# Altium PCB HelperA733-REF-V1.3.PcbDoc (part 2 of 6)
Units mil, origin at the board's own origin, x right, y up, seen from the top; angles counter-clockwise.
Board outline 5905.51 x 4133.86 mil, 2 copper layers (Top, Bottom), stack 12.7 mil thick; 446 components, 341 nets, 1706 pads, 1667 vias.
Unrouted connection lines stored in the file: 1382.
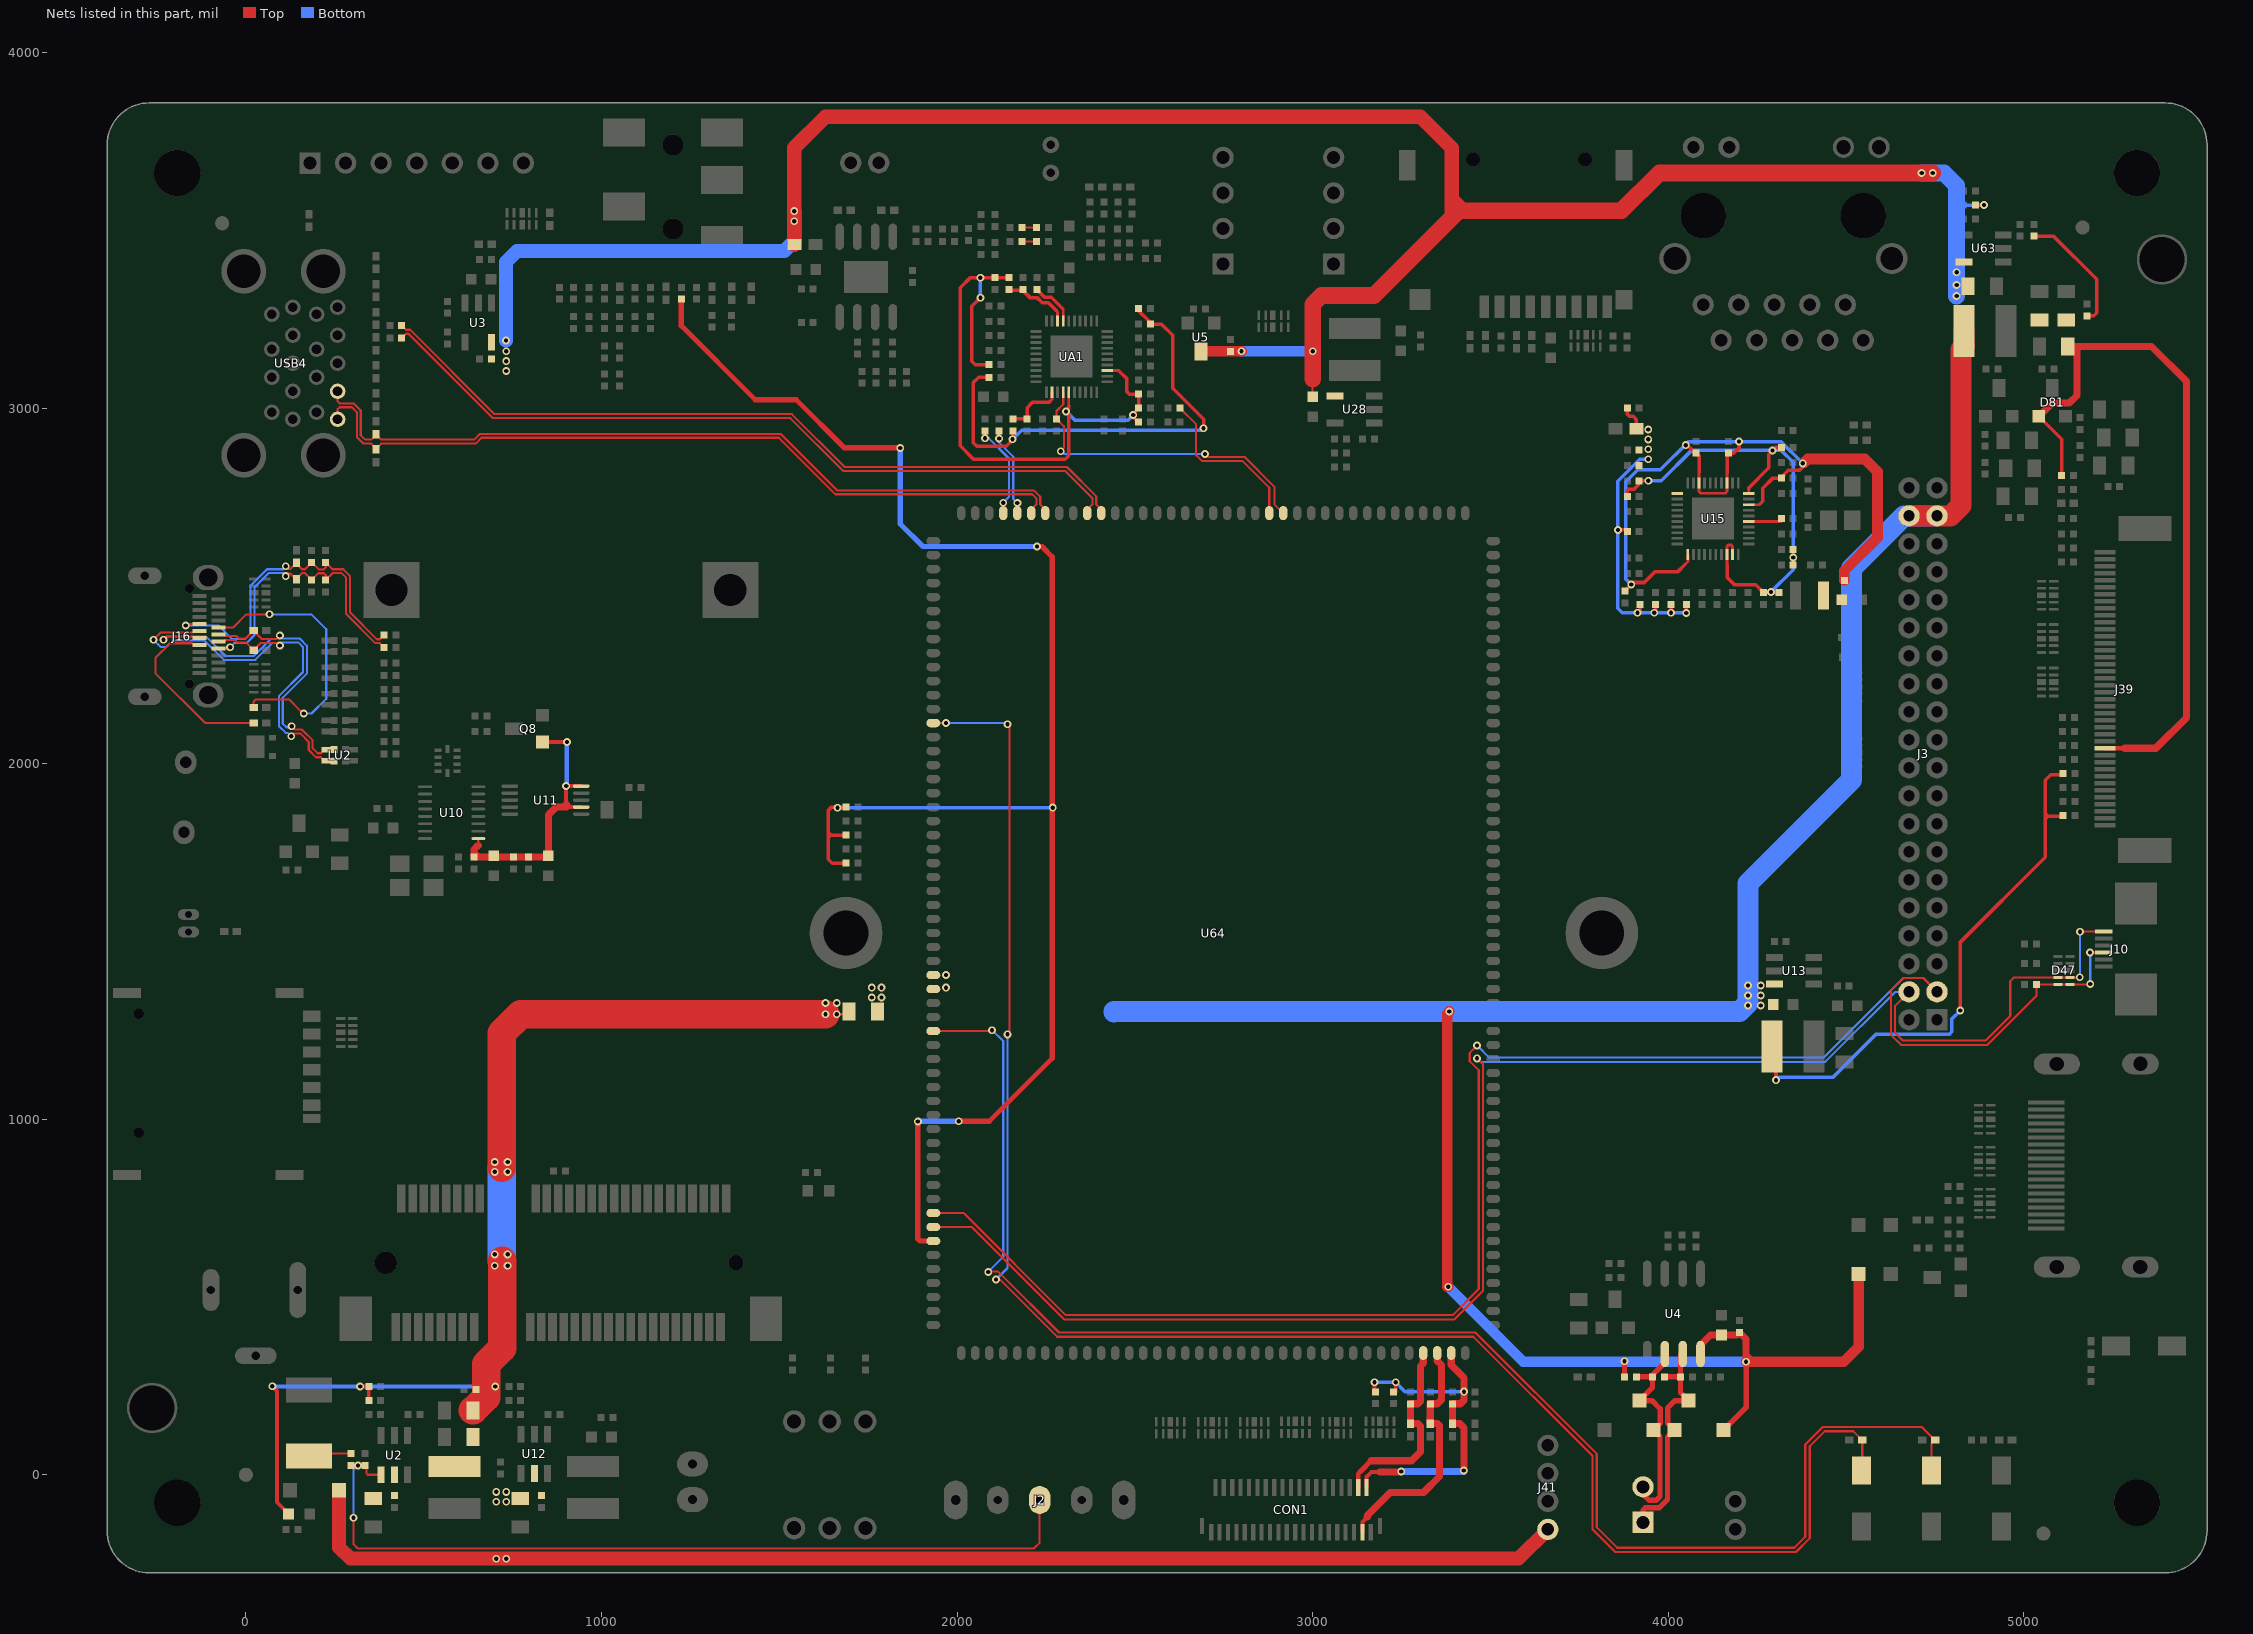
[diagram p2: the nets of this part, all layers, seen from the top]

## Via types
v1: diameter 22, hole 12, Top to Bottom, 1667 vias

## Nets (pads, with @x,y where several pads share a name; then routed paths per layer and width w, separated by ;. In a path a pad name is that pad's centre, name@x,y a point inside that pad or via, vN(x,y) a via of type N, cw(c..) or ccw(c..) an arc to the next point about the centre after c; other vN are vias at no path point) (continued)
5V: C6.1 C35.1 C36.1 C93.1 C95.1 C96.1 C97.1 C216.1 C223.2 C234.1 CU1.2 D3.1 D85.1 D114.2 FB1.2 J3.37 J3.38 L1.2 L4.1 L7.1 R2.1 R42.1 R201.1 R202.1 R210.2 R293.1 U3.5 U4.8 U5.3 U13.6 U28.4 U63.5 | length 18659.5
  Top w6: C96.1@638.43,181.1 638.43,200.34 638.22,200.55 646.65,208.98 C95.1@646.65,240.16 675.46,240.16 684.38,240.16 692.67,248.44 v1(701.28,248.44) ; v1(1629.92,1295.28) v1(1661.42,1295.28) 1698.4,1295.28 1698.4,1300.97 R293.1@1696.22,1303.15 ; C6.1@3000,3031.89 3000,3081.28
  Top w10: v1(74.37,248.93) 87.42,235.88 87.42,-77.05 119.61,-109.24 D3.1@119.61,-110.24 ; v1(321.18,248.36) 345.47,248.36 C93.1@345.47,248.03 R2.1@345.47,208.66 ; L4.1@4291.34,1204.72 4303.13,1204.72 v1(4303.13,1109.95) ; v1(4821.15,1305.5) 4821.15,1497.09 4820.67,1497.09 5060.36,1736.78 5060.36,1844.54 ; R210.2@4864.17,3570.87 v1(4887.9,3570.87) ; R202.1@5110.24,1854.33 5110.24,1852.48 5068.3,1852.48 ; R201.1@5110.24,1972.44 5110.24,1968.99 5075.85,1968.99 5060.36,1953.5 5060.36,1859.62 ; 5060.36,1844.54 5068.3,1852.48 ; 5060.36,1844.54 5060.36,1852.48 ; 5060.36,1852.48 5067.4,1852.48 ; 5060.36,1852.48 5060.36,1859.62 ; 5060.36,1859.62 5067.4,1852.58 5067.4,1852.48 ; 5067.4,1852.48 5068.3,1852.48
  Top w15: R42.1@3876.97,275.59 3876.97,282.12 v1(3877.05,319.56) ; D114.2@4155.61,125.98 4219,189.37 4219,302.88 ; v1(4219,318.12) 4219,302.88 ; 4234.24,318.12 4219,302.88
  Top w20: U4.8@4090.75,339.76 4090.75,365.22 4118.84,393.31 C35.1@4149.61,393.31 ; C35.1@4149.61,394.21 C35.1@4149.61,393.31 ; v1(4219,318.12) 4219,336.95 ; 4234.24,318.12 4234.24,321.71 4219,336.95 ; C35.1@4149.61,393.31 4193.5,393.31 C36.1@4200.79,400.59 4219,382.38 4219,336.95
  Top w23.62: U5.3@2685.96,3158.96 U5.3@2686.61,3159.61
  Top w30: U5.3@2685.96,3158.96 2685.96,3160 v1(2800,3160) ; v1(3381.3,529.12) 3378.88,529.12 3378.27,529.73 3378.27,1297.02 v1(3384.08,1302.83) ; v1(4219,318.12) 4234.24,318.12 4493.57,318.12 4535.43,359.98 D85.1@4535.43,564.86
  Top w40: FB1.2@1542.31,3459.63 1542.31,3732.11 1629.61,3819.41 3302.99,3819.41 3391.21,3731.19 3391.21,3588 ; 3391.21,3588 3391.21,3555.12 3411.68,3555.12 3411.68,3567.54 3391.21,3588
  Top w47.24: 3000,3081.28 v1(3000,3160) 3000,3291.34 3025.02,3316.36 3172.92,3316.36 3411.68,3555.12 3868.72,3555.12 3975.02,3661.42 v1(4712.6,3661.42) v1(4744.09,3661.42)
  Top w59.06: J3.38@4677.17,2696.85 J3.37@4755.91,2696.85 4793.69,2696.85 4823.36,2726.52 4823.36,3165.36 4833,3175 4831.69,3175 L7.1@4831.69,3216.54
  Top w80: C96.1@638.43,181.1 638.87,181.1 675.46,217.69 675.46,240.16 675.46,310.95 720.93,356.42 720.93,601.7 ; 719.79,863.86 719.79,1242.45 772.62,1295.28 v1(1629.92,1295.28)
  Bottom w6: v1(1629.92,1326.77) v1(1629.92,1295.28) v1(1661.42,1326.77)
  Bottom w10: v1(74.37,248.93) 74.94,248.36 v1(321.18,248.36) 701.28,248.36 v1(701.28,248.44) ; v1(4303.13,1109.95) 4311.68,1118.5 4463.29,1118.5 4583.19,1238.4 4790.33,1238.4 4797.72,1245.79 4797.72,1282.07 v1(4821.15,1305.5) ; v1(4811.02,3381.89) 4826.41,3384.31 4826.41,3561.5 ; 4825.51,3582.05 4826.41,3581.15 ; v1(4887.9,3570.87) 4836.69,3570.87 ; 4826.41,3561.5 4826.41,3570.87 ; 4826.41,3561.5 4827.32,3561.5 4836.69,3570.87 ; 4826.41,3570.87 4826.41,3581.15 ; 4826.41,3570.87 4836.69,3570.87 ; 4826.41,3581.15 4836.69,3570.87
  Bottom w30: v1(1542.06,3553.86) v1@1542.25,3553.67 ; v1(2800,3160) v1(3000,3160) ; v1(3381.3,529.12) 3592.3,318.12 v1(4219,318.12)
  Bottom w40: v1(731.71,3190.38) 731.71,3410.91 762.38,3441.58 1514.16,3441.58 1542.25,3469.67 v1(1542.25,3525.62) v1@1542.25,3553.67
  Bottom w47.24: v1(4712.6,3661.42) v1(4744.09,3661.42) 4775.59,3661.42 4811.02,3625.98 v1(4811.02,3381.89) v1(4811.02,3346.46) v1(4811.02,3314.96)
  Bottom w59.06: 2441.97,1301.18 2441.97,1302.83 v1(3384.08,1302.83) 4200.51,1302.83 4224,1326.32 v1(4224,1348) v1(4224,1376) 4224,1662.49 4515.29,1953.78 4515.29,2548.94 4663.2,2696.85 J3.38@4677.17,2696.85 J3.37@4755.91,2696.85
  Bottom w80: 719.29,601.91 719.29,620 719.29,863.36 719.79,863.86
  other v1: 700,588 736,588 700,620 736,620 700,852 736,852 700,880 736,880 4224,1320 4260,1320 4260,1348 4260,1376 732,3104 732,3132 732,3160
5V-IN: R293.2 U64.163 U64.164 | length 0.6
  Top w6: R293.2@1776.22,1303.15 R293.2@1776.22,1303.78
  other v1: 1759.84,1342.52 1787.4,1342.52 1759.84,1370.08 1787.4,1370.08 1968.5,1370.08 1968.5,1405.51
340_3V3: C174.1 C175.1 C176.1 C177.1 C178.1 Q8.1 U10.9 U11.7 U11.10 | length 844.4
  Top w8: 653.54,1770.32 U10.9@653.54,1789.17
  Top w10: 892.38,1877.95 900.14,1880.7 901.72,1881.26 901.72,1877.95
  Top w12: Q8.1@834.28,2060.93 834.42,2060.78 v1(902.87,2060.78) ; 892.38,1877.95 892.38,1882.23 900.14,1889.99 ; 900.14,1880.7 900.14,1889.99 ; 901.72,1877.95 913.03,1877.95 ; U11.7@942.91,1877.95 913.03,1877.95 ; U11.10@942.91,1937.01 v1(900.52,1937.01) 900.14,1936.63 900.14,1889.99 ; 900.14,1889.99 900.99,1889.99 913.03,1877.95
  Top w20: 653.54,1770.32 641.73,1758.51 641.73,1748.62 ; C174.1@696.85,1740.55 C174.1@696.85,1737.2 ; 901.72,1877.95 892.38,1877.95 872.58,1877.95 850.39,1855.76 C176.1@850.39,1740.55 850.39,1737.2 C177.1@795.28,1737.2 C178.1@751.97,1737.2 C174.1@696.85,1737.2 ; 641.73,1748.62 642.28,1748.62 647.71,1743.18 653.69,1737.2 ; 641.73,1748.62 C175.1@641.73,1737.2 653.69,1737.2 ; 653.69,1737.2 C174.1@696.85,1737.2
  Bottom w12: v1(900.52,1937.01) 902.55,1939.04 902.55,2060.46 v1(902.87,2060.78)
485_1+: D115.2 D116.1 J6.2 R42.2 R46.2 U4.6 | length 619.5
  Top w15: R42.2@3910.43,275.59 R46.2@3955.71,275.59 ; J6.2@3929.13,-33.86 3929.13,-54.45 3946.51,-71.83 3965.66,-71.83 3976.85,-60.64 3976.85,107.9 D115.2@3958.76,125.98 3977.37,144.59 3977.37,185.74 3954.45,208.66 D116.1@3919.19,208.66 3955.71,245.18 R46.2@3955.71,275.59 ; U4.6@3990.75,339.76 3990.75,315.94 3952.81,278 3955.95,275.97 3956.54,275.59 R46.2@3955.71,275.59
485_1-: D114.1 D116.2 J6.1 R46.1 R48.2 U4.7 | length 648.3
  Top w15: J6.1@3929.13,-133.86 3929.13,-99.35 3935.58,-92.9 3974.29,-92.9 3997.96,-69.23 3997.96,106.33 D114.1@4017.61,125.98 3998.41,145.19 3998.41,187.53 4019.54,208.66 D116.2@4057.19,208.66 4034.45,231.4 R48.2@4034.45,275.59 ; R46.1@3989.17,275.59 R48.2@4034.45,275.59 ; U4.7@4040.75,339.76 4034.45,339.76 R48.2@4034.45,275.59
AECRN: CA87.2 RA80.1 | length 41.3
  Top w6: CA87.2@2182.09,3468.5 RA80.1@2223.43,3468.5
AECRP: CA84.2 RA79.1 | length 41.3
  Top w6: CA84.2@2182.09,3507.87 RA79.1@2223.43,3507.87
AFVCC-CSI: CON1.36 CP5.1 D175.2 U64.34 | length 566.8
  Top w12: CON1.36@3128.08,-35.4 3128.08,3.16 3134.1,9.18
  Top w15: 3134.1,9.18 3164.51,39.59
  Top w20: 3164.51,39.59 3277.99,39.59 3303.06,64.66 3303.06,136.51 3295.59,143.98 D175.2@3275.59,143.98 CP5.1@3275.59,199.8 3296.3,199.8 3303.15,206.65 3303.15,306.05 3311.02,313.92 U64.34@3311.02,342.52
AGND/VRP: RA8.1 UA1.7 | length 130.2
  Top w8: 2295.72,3281.17 2298.42,3278.47 UA1.7@2298.42,3245.1
  Top w10: RA8.1@2224.41,3333.66 2246.04,3312.03 2264.86,3312.03 2295.72,3281.17
AP-RESET: D5.2 K3.2 U64.167 | length 4384.1
  Top w6: U64.167@1933.07,1248.03 2077.47,1248.03 2098.38,1248.03 v1(2098.38,1250.29) ; v1(2087.47,570.63) 2087.47,572.26 2114.67,572.26 2121.72,565.21 ; 2121.72,565.22 2286.6,400.34 3457.26,400.34 3798.83,58.77 3798.83,-147.74 3856.21,-205.11 4354.24,-205.11 4385.3,-174.05 4385.3,85.21 4434.66,134.57 4712.87,134.57 4749.01,98.43 D5.2@4750.28,98.43 4740.16,88.3 K3.2@4740.16,11.81
  Bottom w6: v1(2087.47,570.63) 2129.77,612.93 2129.77,1219.83 2099.31,1250.29 v1(2098.38,1250.29)
AUXN: C144.2 D9.1 J16.B8 RU24.2 RU110.1 | length 983.7
  Top w6: v1(-169.14,2388.74) -164.1,2392.72 J16.B8@-130.9,2392.72 ; v1(112.17,2555.34) 120.09,2547.42 124.48,2547.42 D9.1@141.73,2564.68 141.73,2562.68 157.57,2546.84 165.93,2546.84 RU110.1@185.04,2565.95 204.58,2546.4 218.96,2546.4 224.41,2551.85 RU24.2@224.41,2565.95 243.52,2546.84 273.56,2546.84 292.9,2527.5 292.9,2425.25 368.16,2349.99 376.56,2349.99 C144.2@388.78,2362.2
  Bottom w6: v1(-169.14,2388.74) -76.84,2388.74 -38.17,2350.07 -3.26,2350.07 13.16,2366.49 13.16,2500.87 59.12,2546.84 105.52,2546.84 106.01,2547.33 v1(112.17,2555.34)
AUXP: C143.2 D8.1 J16.A8 RU23.2 RU25.1 | length 841.5
  Top w6: J16.A8@-77.76,2323.82 -48.07,2323.82 v1(-44.38,2327.51) ; v1(112.17,2527.34) 119.76,2534.93 124.8,2534.93 D8.1@141.73,2518 141.73,2520 157.57,2535.84 165.93,2535.84 RU25.1@185.04,2516.73 203.7,2535.39 219.04,2535.39 224.41,2530.02 RU23.2@224.41,2516.73 243.52,2535.84 269,2535.84 281.77,2523.07 281.77,2420.82 363.6,2338.99 376.56,2338.99 C143.2@388.78,2326.77
  Bottom w6: v1(-44.38,2327.51) -32.82,2339.07 1.49,2339.07 24.19,2361.77 24.19,2496.35 63.68,2535.84 105.15,2535.84 107.22,2533.77 v1(112.17,2527.34)
AVCC: R20.1 R234.1 R278.1 R280.1 U64.182 | length 4680.5
  Top w10: v1(1664,1876) v1@1664,1877.95 ; R280.1@1687.99,1720.47 1687.99,1719.59 1649.14,1719.59 1637.39,1731.35 1637.39,1791.47 ; R278.1@1687.99,1799.21 1645.13,1799.21 ; R234.1@1687.99,1877.95 v1@1664,1877.95 ; 1637.39,1791.47 1645.13,1799.21 ; 1637.39,1791.47 1637.39,1799.21 ; 1637.39,1799.21 1645.13,1799.21 ; 1637.39,1799.21 1637.39,1807.48 ; 1637.39,1807.48 1637.39,1868.4 1646.94,1877.95 v1@1664,1877.95 ; 1637.39,1807.48 1645.13,1799.74 1645.13,1799.21
  Top w15: R20.1@1224.41,3306.1 1224.41,3231.52 1432.47,3023.46 1547.6,3023.46 1683.07,2888 v1(1840,2888) ; v1(1889.68,993.41) 1889.68,663.68 1895.89,657.48 U64.182@1933.07,657.48 ; v1(2004.78,994.29) 2090.42,994.29 2267.59,1171.47 2267.59,2581.72 2238.65,2610.66 v1(2224.72,2610.66)
  Bottom w10: v1(1664,1876) 2268.97,1876 v1(2268.97,1876.29) ; v1(2004.78,994.29) v1@2005.29,994.8
  Bottom w15: v1(1840,2888) 1840,2674.8 1904.14,2610.66 v1(2224.72,2610.66) ; v1(1889.68,993.41) 1888.84,993.41 1888.84,994.29 v1(2004.78,994.29)
AVCC/VRA1: CA14.1 RA16.2 UA1.8 | length 188.9
  Top w8: 2278.25,3274.7 2282.67,3270.28 UA1.8@2282.67,3245.1
  Top w10: RA16.2@2145.67,3333.66 2147.61,3331.72 2185.04,3331.72 2185.04,3330.85 2205.04,3310.85 2224.6,3310.85 2239.41,3296.03 2256.92,3296.03 2278.25,3274.7
AVDD: C54.1 C59.1 C230.1 D81.1 D125.2 J39.29 R199.1 R207.2 | length 2390.9
  Top w10: R207.2@5028.54,3483.27 5083.66,3483.27 5204.72,3362.2 5204.72,3267.72 5196.85,3259.84 5179.13,3259.84 C54.1@5178.15,3258.86 ; D81.1@5042.22,2976.75 5106.3,2912.67 R199.1@5106.3,2811.02
  Top w12: J39.29@5228.35,2043.31 5228.35,2043.18 5283.1,2043.18
  Top w20: D81.1@5042.22,2976.75 5079.3,3013.82 5127.35,3013.82 5149.23,3035.7 5149.23,3166.37 ; D125.2@5123.66,3173.23 5359.43,3173.23 5458.01,3074.64 5458.01,2130.12 5371.07,2043.18 5283.1,2043.18
AVDD10: CE4.2 CE5.2 CE7.2 CE8.2 CE20.2 CE21.2 L3.2 U15.3 U15.8 U15.21 U15.38 | length 2292.7
  Top w8: 4046.02,2559.11 4055.12,2568.21 U15.21@4055.12,2588.58 ; 4086.61,2819.82 4086.61,2765.52 4091.6,2760.53 4160.66,2760.53 4165.35,2765.22 U15.3@4165.35,2789.37 4165.35,2816.13 ; U15.38@4226.38,2728.35 4256.53,2728.35 4257.81,2729.63
  Top w10: CE21.2@3877.95,2485.24 3902.13,2509.41 3932.11,2509.41 3961.84,2539.14 4026.05,2539.14 4046.02,2559.11 ; v1(4049.09,2895.83) 4054.16,2895.83 4077.85,2872.14 4077.85,2873.03 CE4.2@4078.74,2873.03 4086.61,2865.16 4086.61,2819.82 ; 4165.35,2816.13 4165.35,2869.09 CE5.2@4169.29,2873.03 4184.39,2873.03 4199.21,2887.85 v1(4199.21,2905.78) ; 4257.81,2729.63 4265.79,2737.61 4265.79,2774.47 4294.47,2803.15 CE20.2@4317.91,2803.15 4317.91,2804.04 4317.02,2804.04 4337.78,2824.8 4369.26,2824.8 4378.36,2833.9 v1(4378.36,2844.5)
  Top w30: v1@4382.22,2846.7 4392.18,2856.66 4552.23,2856.66 4588.34,2820.55 4588.34,2635.93 4495.08,2542.67 CE8.2@4495.08,2515.75
  Bottom w10: v1(3896,2504) 3880.87,2519.13 3880.87,2792.74 3914.24,2826.11 3977.25,2826.11 4056.92,2905.78 v1(4199.21,2905.78) 4317.07,2905.78 v1(4378.36,2844.5)
AVDD33: CE9.2 CE11.2 CE12.2 CE13.2 CE14.2 CE15.2 FB2.2 R81.2 R149.1 RE18.1 RE20.1 RE21.1 RE25.2 RE36.2 RE38.2 RE40.2 U15.11 U15.28 U15.29 U15.40 | length 2325.2
  Top w8: 4166.22,2560.8 4165.51,2563.34 4165.51,2588.43 U15.28@4165.35,2588.58 4165.35,2611.08 4168.74,2614.47 4177.62,2614.47 4181.1,2610.99 U15.29@4181.1,2588.58 ; U15.40@4226.38,2759.84 4226.38,2771.47
  Top w10: v1(3858.86,2657.03) 3858.86,2657.51 3884.84,2657.51 RE21.1@3884.84,2653.54 ; RE18.1@3884.84,2751.97 3884.84,2767.57 3889.48,2772.21 3904.87,2772.21 3916.03,2783.37 CE15.2@3916.03,2799.33 ; R81.2@3884.84,3000 3884.84,2983.21 3891.28,2976.77 3901.47,2976.77 3910.45,2967.79 FB2.2@3910.45,2941.94 ; v1(3913.52,2424.45) 3921.26,2432.18 RE25.2@3921.26,2447.84 ; CE15.2@3918.31,2795.28 3918.31,2795.8 v1(3944.07,2795.8) ; v1(3960.76,2424.25) 3964.57,2428.06 RE36.2@3964.57,2447.84 ; RE38.2@4007.87,2447.84 4008.03,2447.84 v1(4008.03,2424.28) ; v1(4050.81,2423.95) 4050.81,2447.84 RE40.2@4051.18,2447.84 ; 4166.22,2560.8 4166.22,2523.4 4186.32,2503.3 4245.71,2503.3 CE14.2@4267.72,2481.3 CE12.2@4311.02,2481.3 ; 4226.38,2771.47 4226.38,2775.4 4283.06,2832.08 4283.06,2869.75 4293.76,2880.45 4303.07,2889.76 CE9.2@4317.91,2889.76 ; RE20.1@4351.38,2559.06 4351.48,2559.06 v1(4351.48,2579.93) 4351.48,2602.36 R149.1@4351.38,2602.36
  Bottom w10: v1(3944,2856) 3920.21,2856 3858.27,2794.05 3858.27,2657.03 v1(3858.86,2657.03) 3858.27,2653.54 3858.27,2437.14 3870.97,2424.45 v1(3913.52,2424.45) 3960.76,2424.45 v1(3960.76,2424.25) 3963.63,2424.28 v1(4008.03,2424.28) 4008.36,2423.95 v1(4050.81,2423.95) ; v1(3944.07,2795.8) 3980.24,2795.8 4065.23,2880.79 v1(4293.42,2880.79) 4317.97,2880.79 4351.48,2847.28 v1(4351.48,2579.93) 4351.48,2545.42 v1(4289.06,2483)
  other v1: 3944,2884 3944,2912 3944,2940
AVDD-CSI: CON1.38 CP7.1 D177.2 R8.1 R9.1 U64.36 | length 1033.3
  Top w6: R9.1@3227.72,233.49 R9.1@3231.65,233.49
  Top w10: v1(3173.86,260.24) 3173.86,233.49 R8.1@3176.54,233.49 ; R9.1@3231.65,233.49 3233.66,233.49 v1(3233.66,260.09)
  Top w12: CON1.38@3151.7,-35.4 3151.7,-5.78 3165.57,8.09 3188.35,8.09
  Top w20: 3188.35,8.09 3248.21,8.09 v1(3249.29,9.18) ; U64.36@3389.76,342.52 3389.76,308.49 3425.45,272.8 v1(3425.45,233.88) 3425.45,209.64 3415.62,199.8 CP7.1@3393.7,199.8 D177.2@3393.7,143.98 3413.7,143.98 3425.57,132.12 3425.57,12.07 v1(3425.03,12.07)
  Bottom w10: v1(3173.86,260.24) 3233.66,260.24 v1(3233.66,260.09) 3259.87,233.88 v1(3425.45,233.88)
  Bottom w20: v1(3249.29,9.18) 3425.03,9.18 v1(3425.03,12.07)
CC1: D10.1 J16.A5 | length 789.6
  Top w6: J16.A5@-77.76,2382.88 -35.87,2382.88 1.24,2419.99 v1(66.1,2419.99) ; D10.1@21.37,2157.34 D10.1@21.37,2157.48 21.37,2174.32 27.51,2180.46 121.93,2180.46 154.6,2147.79 155.13,2148.32 v1(162.36,2141.1)
  Bottom w6: v1(66.1,2419.99) 183.83,2419.99 225.72,2378.1 225.72,2182.49 184.33,2141.1 v1(162.36,2141.1)
CC2: D11.1 J16.B5 | length 519.7
  Top w6: J16.B5@-130.9,2333.66 -132.8,2335.56 -149.18,2335.56 -152.19,2338.58 -213.02,2338.58 -254.61,2296.99 -254.61,2254.27 -114.51,2114.17 D11.1@21.37,2114.17
CLKOUT-125M: RE15.2 U15.35 | length 99.4
  Top w8: U15.35@4226.38,2681.1 4317.91,2681.1 RE15.2@4317.91,2688.98
CODEC-AVCC: CA18.2 RA10.2 RA14.1 RA16.1 RA17.2 RA102.2 UA1.25 UA1.33 | length 1840.3
  Top w6: RA14.1@2508.67,2960.63 RA14.1@2510.83,2960.63
  Top w8: 2314.17,3006.25 UA1.25@2314.17,3044.32 ; UA1.33@2422.44,3105.34 2455.11,3105.34
  Top w10: v1(2065.73,3310.39) 2041.34,3286.01 2041.34,3131.95 2051.24,3122.05 RA10.2@2089.57,3122.05 ; RA16.1@2145.67,3367.13 RA102.2@2106.3,3367.13 2065.52,3367.13 v1(2065.52,3366.6) 2058.85,3367.13 2037.9,3367.13 2008.94,3338.17 2008.94,2893.63 2046.07,2856.5 2303.85,2856.5 2314.17,2866.82 2314.17,2982.73 v1(2306.49,2990.41) 2306.74,2990.41 2314.17,2997.84 2314.17,3006.25 ; 2455.11,3105.34 2477.75,3082.7 2477.75,3045.89 2484.27,3039.37 CA18.2@2508.89,3039.37 ; RA14.1@2508.67,2960.63 2495.16,2974.14 v1(2495.16,2980.36) 2495.16,2984.33 RA17.2@2510.83,3000 CA18.2@2510.83,3039.37 ; CA18.2@2510.18,3038.08 2509.86,3038.4 CA18.2@2508.89,3039.37 ; CA18.2@2514.76,3039.37 CA18.2@2510.83,3039.37 ; CA18.2@2508.89,3039.37 CA18.2@2510.83,3039.37
  Bottom w10: v1(2065.52,3366.6) 2065.73,3366.4 v1(2065.73,3310.39) ; v1(2306.49,2990.41) 2330.58,2966.32 2481.12,2966.32 v1(2495.16,2980.36)
CODEC-CPVDD: RA9.1 RA15.1 RA18.1 RA103.2 | length 1358
  Top w10: RA9.1@2089.57,3086.61 2060.77,3086.61 2045.89,3071.73 2045.89,2902.17 2055.83,2892.23 2138.28,2892.23 2157.48,2911.44 RA15.1@2157.48,2936.02 ; RA103.2@2510.83,3279.53 2513.34,3279.53 2511.3,3278.55 2507.51,3276.72 2544.65,3239.58 2545.43,3238.24 RA18.1@2544.29,3236.22 2574.73,3236.22 2606.29,3204.66 2606.29,3055.92 2693.3,2968.91 v1(2693.3,2943.42)
  Bottom w10: v1(2155.82,2912.42) 2181.48,2938.08 2690.25,2938.08 2694.44,2942.27 v1(2693.3,2943.42)
CODEC-IRQ: RA29.2 U64.108 UA1.24 | length 913.8
  Top w6: v1(2291.34,2878.53) 2300.17,2887.36 2300.17,2948.85 RA29.2@2279.53,2969.49 2279.53,2991.81 2298.42,3010.7 UA1.24@2298.42,3044.32 ; v1(2697.21,2871.03) 2705.48,2862.76 2808.12,2862.76 2892.41,2778.47 2892.41,2729.63 U64.108@2917.32,2704.73
  Bottom w6: v1(2291.34,2878.53) 2292.97,2880.16 2302.1,2871.03 v1(2697.21,2871.03)
CODEC-RST: RA20.2 U64.109 | length 466.1
  Top w6: RA20.2@2626.97,3000 2672.33,2954.64 2672.33,2867.46 2689.03,2850.76 2803.15,2850.76 2877.95,2775.96 U64.109@2877.95,2704.73
COMB1-REFN: R165.2 U64.128 | length 272.4
  Top w6: v1(2078.66,2915) 2078.58,2915 2078.58,2935.86 R165.2@2078.74,2936.02 ; v1(2129.79,2733.86) 2129.92,2733.86 U64.128@2129.92,2704.73
  Bottom w6: v1(2078.66,2915) 2089.21,2915 2146.08,2858.13 2146.08,2750.15 v1(2129.79,2733.86)
COMB1-REFP: R166.2 U64.127 | length 270.1
  Top w6: R166.2@2118.11,2936.02 2117.7,2942.37 2117.7,2911.9 v1(2118.3,2914.24) ; U64.127@2169.29,2704.73 2169.29,2733.09 v1(2169.47,2733.09)
  Bottom w6: v1(2118.3,2914.24) 2118.3,2902.88 2158.1,2863.08 2158.1,2744.46 v1(2169.47,2733.09)
COMB1-RX0N: D72.1 U64.126 USB4.14 | length 2216.7
  Top w6: USB4.14@257.87,2968.5 257.87,2996.87 263.37,3002.37 298.09,3002.37 312.01,2988.45 312.01,2918.77 330.61,2900.17 352.39,2900.17 D72.1@366.26,2886.3 ; D72.1@366.26,2884.3 D72.1@366.26,2886.3 ; U64.126@2208.66,2704.73 2208.66,2714.56 2222.84,2728.75 2222.84,2745.97 2211.16,2757.66 1657.6,2757.66 1498.82,2916.44 662.62,2916.44 646.35,2900.17 380.13,2900.17 D72.1@366.26,2886.3
COMB1-RX0P: D73.1 U64.125 USB4.15 | length 2235
  Top w6: USB4.15@257.87,3047.24 257.87,3018.87 263.37,3013.37 302.64,3013.37 323.01,2993.01 323.01,2923.33 335.17,2911.17 352.39,2911.17 D73.1@366.26,2925.04 ; D73.1@366.26,2927.04 D73.1@366.26,2925.04 ; U64.125@2248.03,2704.73 2248.03,2714.56 2233.84,2728.75 2233.84,2750.53 2215.71,2768.66 1662.19,2768.66 1503.32,2927.53 1464.57,2927.53 658.14,2927.52 641.79,2911.17 380.13,2911.17 D73.1@366.26,2925.04
COMB1-TX0N: C213.1 U64.122 | length 2186.9
  Top w6: C213.1@438.11,3197.01 450.33,3209.22 457.14,3209.22 694.77,2971.59 1531.07,2971.59 1679.53,2823.13 2304.23,2823.13 2380.32,2747.04 2380.32,2728.75 2366.14,2714.56 U64.122@2366.14,2704.73
COMB1-TX0P: C214.1 U64.121 | length 2205.2
  Top w6: C214.1@438.11,3232.44 450.33,3220.22 461.7,3220.22 698.95,2982.97 1535.32,2982.97 1684.17,2834.13 2308.94,2834.13 2391.32,2751.75 2391.32,2728.75 2405.51,2714.56 U64.121@2405.51,2704.73
CPVDD: CA13.1 RA15.2 UA1.22 | length 170.6
  Top w8: 2261.57,3018.97 2266.92,3024.32 UA1.22@2266.92,3044.32
  Top w10: RA15.2@2157.48,2969.49 CA13.1@2196.85,2969.49 2196.85,3000.95 2212.27,3016.38 2258.73,3016.38 2261.33,3018.97 2261.57,3018.97
CTP0-INT: D47.5 D47.6 J3.3 J10.4 R213.1 U64.180 | length 4879.8
  Top w6: U64.180@1933.07,736.22 2018.6,736.22 2305.71,449.11 3393.61,449.11 3467.14,522.64 3467.14,1137.79 3441.93,1163 3441.93,1186.73 v1(3462.5,1207.3) ; J3.3@4755.91,1358.27 4716.91,1397.27 4661.01,1397.27 4626.05,1362.31 4626.05,1238.03 4655.17,1208.91 4897.59,1208.91 5035.21,1346.53 R213.1@5035.21,1379.2 D47.5@5095.93,1379.2 5186.83,1379.2 v1(5186.83,1380.06) ; v1(5186.19,1469.07) 5186.75,1468.5 J10.4@5224.41,1468.5
  Bottom w6: v1(3462.5,1207.3) 3496.61,1173.19 4436.63,1173.19 4660.71,1397.27 4716.91,1397.27 J3.3@4755.91,1358.27 ; v1(5186.19,1469.07) 5186.83,1469.07 v1(5186.83,1380.06)
CTP0-RST: D47.4 D47.7 J3.4 J10.1 U64.181 | length 4640.8
  Top w6: U64.181@1933.07,696.85 2041,696.85 2300.75,437.1 3398.7,437.1 3479.14,517.54 3479.14,1154.24 v1(3462.19,1171.19) ; J3.4@4677.17,1358.27 4638.1,1319.2 4638.1,1243.1 4660.25,1220.95 4892.46,1220.95 4962.01,1290.5 4962.01,1388.47 4972.42,1398.88 D47.4@5095.93,1398.88 D47.7@5130.01,1398.88 5160.56,1398.88 5160.56,1399.11 v1(5157.32,1399.44) ; v1(5157.71,1527.32) 5157.95,1527.56 J10.1@5224.41,1527.56
  Bottom w6: v1(3462.19,1171.19) 3472.19,1161.19 4441.97,1161.19 4639.05,1358.27 J3.4@4677.17,1358.27 ; v1(5157.32,1399.44) 5157.71,1399.83 v1(5157.71,1527.32)
D+: D6.1 J16.A6 J16.B6 LU2.1 RU19.2 | length 1210.1
  Top w6: v1(-231.51,2348.4) -222.21,2357.69 -150.92,2357.69 -146.57,2353.35 J16.B6@-130.9,2353.35 ; J16.A6@-77.76,2363.19 -61.44,2363.19 -57.1,2358.85 -27.03,2358.85 -20.14,2351.96 -0.69,2351.96 D6.1@21.37,2374.02 44.66,2350.73 85.75,2350.73 v1(95.47,2360.46) ; v1(128.5,2105.21) 137.48,2096.23 156.83,2096.23 187.54,2065.53 187.54,2043.34 201.76,2029.12 210.23,2029.12 220.47,2039.36 LU2.1@227.36,2039.36
  Bottom w6: v1(-231.51,2348.4) -222.69,2357.21 -111.93,2357.21 -57.59,2302.88 21.91,2302.88 69.45,2350.42 85.44,2350.42 v1(95.47,2360.46) 103.97,2351.96 151.37,2351.96 171.36,2331.97 171.36,2253.15 103.55,2185.34 103.55,2112.32 113.95,2101.92 131.54,2101.92 134.78,2105.16 v1(128.5,2105.21)
D-: D7.1 J16.A7 J16.B7 LU2.2 RU22.2 | length 1278.7
  Top w6: v1(-260.23,2348.48) -240.02,2368.7 -149.26,2368.7 -144.92,2373.04 J16.B7@-130.9,2373.04 ; J16.A7@-77.76,2343.51 -61.88,2343.51 -57.54,2347.85 -31.88,2347.85 -24.99,2340.96 -0.69,2340.96 D7.1@21.37,2318.9 42.19,2339.72 88.21,2339.72 v1(95.47,2332.46) ; v1(127.41,2077.15) 125.02,2077.26 132.81,2085.05 152.33,2085.05 176.54,2060.84 176.54,2038.24 196.65,2018.12 210.23,2018.12 220.47,2007.88 LU2.2@227.36,2007.88
  Bottom w6: v1(-260.23,2348.48) -240.15,2328.4 -223.21,2328.4 -205.47,2346.13 -116.65,2346.13 -62.39,2291.88 26.58,2291.88 74.09,2339.39 85.48,2339.39 93.24,2331.63 94.65,2331.63 v1(95.47,2332.46) 103.97,2340.96 146.76,2340.96 160.3,2327.42 160.3,2257.65 92.52,2189.87 92.52,2106.01 111.87,2086.66 117.9,2086.66 v1(127.41,2077.15)
DC_EN: J2.2 R5.1 R158.2 U2.4 | length 2394.7
  Top w6: R158.2@295.28,26.58 295.28,26.51 v1(314.87,26.51) 314.94,26.58 R5.1@334.65,26.58 338.58,22.64 338.58,3.94 342.52,0 U2.4@379.92,0 ; v1(302.78,-120.77) 302.78,-195.24 314.78,-207.24 2215.8,-207.24 2232.28,-190.76 J2.2@2232.28,-70.87
  Bottom w6: v1(302.78,-120.77) 302.78,14.42 v1(314.87,26.51)
DCIN: C90.1 C94.1 C190.1 C193.1 D2.2 F1.2 J41.1 R158.1 U2.5 U12.5 | length 3728.5
  Top w6: F1.2@177.17,53.17 184.04,60.04 R158.1@295.28,60.04
  Top w39.37: D2.2@261.91,-43.31 261.91,-203.9 294.01,-236 v1(704,-236) v1(732,-236) 3578.96,-236 J41.1@3661.42,-153.54
  other v1: 704,-76 732,-76 704,-48 732,-48
DVDD-CSI: CON1.37 CP6.1 D176.2 U64.35 | length 700.9
  Top w12: CON1.37@3139.89,-161.38 3139.89,-132.61 3153.51,-118.99
  Top w20: 3153.51,-118.99 3153.92,-113.5 3217.17,-50.25 3311.07,-50.25 3356.71,-4.61 3356.71,137.98 3350.71,143.98 D176.2@3330.71,143.98 CP6.1@3330.71,199.8 3351.01,199.8 3362.19,210.98 3362.19,308.64 3350.39,320.44 U64.35@3350.39,342.52
FEL: D1.1 K1.1 U64.145 | length 5068.6
  Top w6: U64.145@1933.07,2114.17 v1(1969.01,2114.17) ; v1(2109.27,549.29) 2109.27,550.91 2119.06,550.91 2281.7,388.27 3452.02,388.27 3786.83,53.46 3786.83,-152.71 3851.24,-217.11 4359.21,-217.11 4397.85,-178.47 4397.85,80.65 4439.77,122.57 4520.14,122.57 4544.29,98.43 D1.1@4545.56,98.43 4545.56,14.06 K1.1@4543.31,11.81 ; v1(2141.67,2110.61) 2141.35,2110.29 2147.07,2104.57 2147.07,1240.83 2143.35,1237.11 v1(2141.77,1238.7)
  Bottom w6: v1(1969.01,2114.17) 2145.18,2114.17 2145.18,2113.83 2141.42,2113.5 v1(2141.67,2110.61) ; v1(2109.27,549.29) 2141.77,581.79 v1(2141.77,1238.7)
